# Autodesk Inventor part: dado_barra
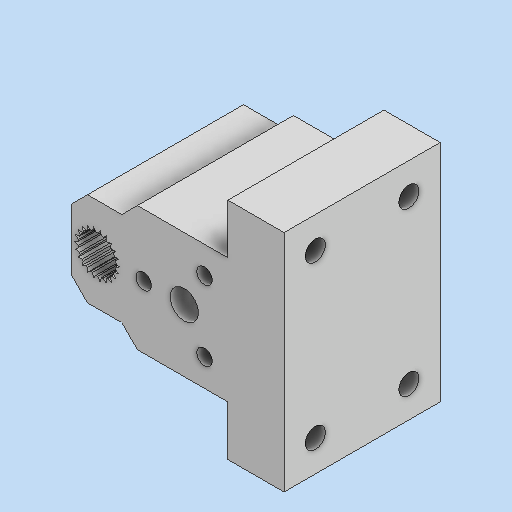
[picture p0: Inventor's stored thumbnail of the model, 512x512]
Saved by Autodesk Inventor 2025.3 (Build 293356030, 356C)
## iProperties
Created: 2025-12
Part Number: dado_barra
Material: Generico
Document SubType Name: Modeling
Designer: Ryzen5700u
Density: 1 g/cm^3
Appearance: Default
Author: Ryzen5700u
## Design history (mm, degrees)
sketch "Schizzo1"
  geometry: L1 (-10, 10)-(10, 10); L2 (10, 10)-(10, -10); L3 (10, -10)-(-10, -10); L4 (-10, -10)-(-10, 10); L5 (-10, 10)-(10, -10); L6 (10, 10)-(-10, -10); L7 (-10, 7.5)-(-18, 7.5); L8 (-18, 7.5)-(-18, -7.5); L9 (-18, -7.5)-(-10, -7.5); L10 (-10, -7.5)-(-10, 7.5); L11 (0, 0)-(-22.766, 0); C1 r 1.621 at (-14, 0) reference; C2 r 3 at (-14, 0); C3 r 1.23 at (3.25, 5.629) reference; C4 r 1.23 at (3.25, -5.629) reference; C5 r 1.23 at (-6.5, 0) reference; C6 r 2.25 at (0, 0); 1 further point
  constraints: 22 end point, 4 parallel, 3 horizontal, 2 centre point, 2 coincident, 2 midpoint, 2 perpendicular, 1 point on line, 1 other
  dimensions: "d0" = 20 distance of L2.end L3.end; "d1" = 20 distance of L1.end L2.end; "d2" = 8 distance of L9.end L8.end; "d3" = 15 distance of L8.end L7.end; "d4" = 6 diameter of C2; "d7" = 4.5 diameter of C6
extrude "Estrusione1" new body sketch "Schizzo1" distance "d5" = 25; taper "d6" = 0 deg
sketch "Schizzo2"
  geometry: L1 (-14, 0)-(-6.5, 0); L2 (-14, 0.3)-(-6.5, 0.3); L3 (-14, -0.3)-(-6.5, -0.3); L4 (-11.015, -0.3)-(-10.416, 0); L5 (-11.015, 0.3)-(-10.416, 0); C1 r 1.23 at (-6.5, 0) reference; A1 r 3 centre (-14, 0) between (-11.015, -0.3) and (-11.015, 0.3) reference; 1 further point
  constraints: 10 end point, 3 point on line, 2 parallel, 2 point on circle, 1 horizontal
  dimensions: "d9" = 0.3 distance between parallel lines of L1 L2; "d10" = 0.3 distance between parallel lines of L1 L3
extrude "Estrusione2" cut sketch "Schizzo2" extent not by distance; stored distance "d11" = 0; taper "d12" = 0 deg
chamfer "Smusso1" distance "d16" = 2.5; stored, may be unused: second distance "d17" = 2, angle "d18" = 45 deg
sketch "Schizzo3"
  geometry: L1 (0, 0)-(0, 20) reference; L2 (0, 20)-(-25, 20) reference; L3 (-25, 0)-(-25, 20) reference; L4 (0, 0)-(-25, 0) reference; L5 (-25, 28)-(0, 28); L6 (0, 28)-(0, -8); L7 (0, -8)-(-25, -8); L8 (-25, -8)-(-25, 28); L9 (-25, 10)-(0, 10) reference; L10 (-25, 28)-(0, -8); L11 (0, 28)-(-25, -8); 5 further points
  constraints: 12 end point, 3 midpoint, 2 parallel, 1 horizontal, 1 perpendicular
  dimensions: "d30" = 36 distance of L5.end L6.end
extrude "Estrusione3" join sketch "Schizzo3" distance "d19" = 6; taper "d20" = 0 deg; dims "d34" = 3, "d35" = 0
sketch "Schizzo4"
  geometry: L1 (-25, 20)-(0, 20) reference; L2 (-25, 0)-(-25, 2.5) reference; L3 (0, 20)-(-25, 0); L4 (0, 0)-(-25, 0) reference; L5 (-25, 0)-(0, 0); L6 (0, 0)-(-25, 20); L7 (-20, 23)-(-5, 23); L8 (-5, 23)-(-5, -3); L9 (-5, -3)-(-20, -3); L10 (-20, -3)-(-20, 23); L11 (-20, 23)-(-5, -3); L12 (-5, 23)-(-20, -3); 3 further points
  constraints: 18 end point, 3 equal length, 3 midpoint, 1 horizontal, 1 perpendicular
  dimensions: "d21" = 15 distance of L8.end L9.end; "d22" = 26 distance of L7.end L8.end
hole "Foro1" sketch "Schizzo4" at (-5, -3), (-5, 23), (-20, -3), (-20, 23) diameter "d23" = 3.2; stored, may be unused: countersink angle "d27" = 90 deg, drill point angle "d29" = 0 deg; dims "d24" = 6, "d25" = 4, "d26" = 2, "d28" = 5.5
chamfer "Smusso2" distance "d31" = 5; stored, may be unused: second distance "d32" = 2, angle "d33" = 45 deg
sketch "Schizzo5" dims "d36" = 5.5, "d37" = 5.5, "d38" = 5.5, "d39" = 5.5
  geometry: L1 (2.25, -3)-(3.625, -0.618); L2 (3.625, -0.618)-(6.375, -0.618); L3 (6.375, -0.618)-(7.75, -3); L4 (7.75, -3)-(6.375, -5.382); L5 (6.375, -5.382)-(3.625, -5.382); L6 (3.625, -5.382)-(2.25, -3); L7 (17.25, -3)-(18.625, -0.618); L8 (18.625, -0.618)-(21.375, -0.618); L9 (21.375, -0.618)-(22.75, -3); L10 (22.75, -3)-(21.375, -5.382); L11 (21.375, -5.382)-(18.625, -5.382); L12 (18.625, -5.382)-(17.25, -3); L13 (2.25, 22.981)-(3.608, 25.372); L14 (3.608, 25.372)-(6.358, 25.391); L15 (6.358, 25.391)-(7.75, 23.019); L16 (7.75, 23.019)-(6.392, 20.628); L17 (6.392, 20.628)-(3.642, 20.609); L18 (3.642, 20.609)-(2.25, 22.981); L19 (17.25, 22.981)-(18.608, 25.372); L20 (18.608, 25.372)-(21.358, 25.391); L21 (21.358, 25.391)-(22.75, 23.019); L22 (22.75, 23.019)-(21.392, 20.628); L23 (21.392, 20.628)-(18.642, 20.609); L24 (18.642, 20.609)-(17.25, 22.981); C1 r 1.6 at (5, -3) reference; C2 r 1.6 at (5, 23) reference; C3 r 1.6 at (20, 23) reference; C4 r 1.6 at (20, -3) reference; 9 further points
  constraints: 48 end point, 8 coincident, 2 horizontal alignment, 1 point on line, 62 other
extrude "Estrusione4" cut sketch "Schizzo5" distance "d40" = 3; taper "d41" = 0 deg
node "Solido1"
pattern_circular "Serie circolare1" dims angle "d14" = 360 deg
node "Riferimento1"
node "Riferimento2"
node "Riferimento3"
node "Riferimento4"
node "Linea chiusa proiettata1"
